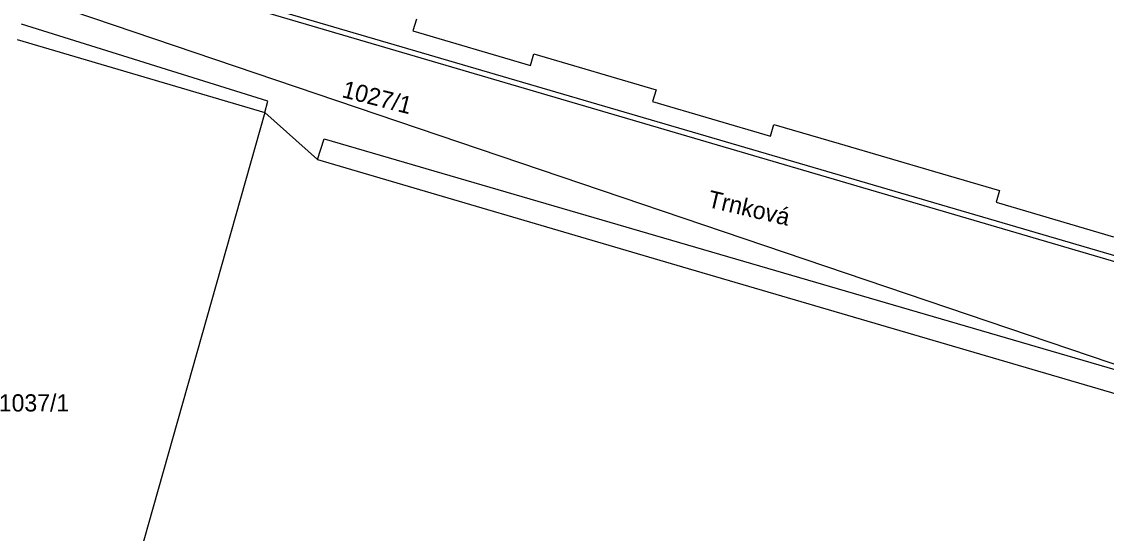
# Model space of a CAD drawing. Extents: x -469926 to -462499, y -1098642 to -1092733.
# Drawn here: x -465329.9 to -465222.8, y -1095231.4 to -1095180.8 of the extents above; entities that cross this region are included whole.
import ezdxf

# ---------------------------------------------------------------- set-up
doc = ezdxf.new("R2010")
doc.units = 0
for name, color, linetype in [('Vrstva 1', 7, 'Continuous'), ('Vrstva 4', 7, 'Continuous'), ('Vrstva 50', 7, 'Continuous'), ('Vrstva 6', 7, 'Continuous'), ('Vrstva 8', 7, 'Continuous')]:
    doc.layers.add(name, color=color, linetype=linetype)

msp = doc.modelspace()

# ---------------------------------------------------------------- linework, layer by layer
at = {"layer": 'Vrstva 1'}
for p, q in [((-465290.92, -1095180.57), (-465291.27, -1095181.74)), ((-465290.92, -1095180.57), (-465291.27, -1095181.74)), ((-465291.27, -1095181.74), (-465279.67, -1095185.14)), ((-465291.27, -1095181.74), (-465279.67, -1095185.14)), ((-465330.39, -1095182.57), (-465305.92, -1095189.78)), ((-465279.67, -1095185.14), (-465279.32, -1095183.99)), ((-465279.67, -1095185.14), (-465279.32, -1095183.99)), ((-465279.32, -1095183.99), (-465267.25, -1095187.55)), ((-465279.32, -1095183.99), (-465267.25, -1095187.55)), ((-465267.25, -1095187.55), (-465267.59, -1095188.7)), ((-465267.25, -1095187.55), (-465267.59, -1095188.7)), ((-465267.59, -1095188.7), (-465255.95, -1095192.13)), ((-465267.59, -1095188.7), (-465255.95, -1095192.13)), ((-465305.92, -1095189.78), (-465325.28, -1095258.28)), ((-465305.92, -1095189.78), (-465325.28, -1095258.28)), ((-465305.92, -1095189.78), (-465300.7, -1095194.45)), ((-465305.92, -1095189.78), (-465300.7, -1095194.45)), ((-465255.95, -1095192.13), (-465255.61, -1095190.99)), ((-465255.95, -1095192.13), (-465255.61, -1095190.99)), ((-465255.61, -1095190.99), (-465249.16, -1095192.86)), ((-465255.61, -1095190.99), (-465249.16, -1095192.86)), ((-465249.16, -1095192.86), (-465239.73, -1095195.62)), ((-465249.16, -1095192.86), (-465239.73, -1095195.62)), ((-465300.7, -1095194.45), (-465264.63, -1095205.04)), ((-465300.7, -1095194.45), (-465264.63, -1095205.04)), ((-465239.73, -1095195.62), (-465233.31, -1095197.5)), ((-465239.73, -1095195.62), (-465233.31, -1095197.5)), ((-465233.31, -1095197.5), (-465233.65, -1095198.64)), ((-465233.31, -1095197.5), (-465233.65, -1095198.64)), ((-465233.65, -1095198.64), (-465222.05, -1095202.07)), ((-465233.65, -1095198.64), (-465222.05, -1095202.07)), ((-465264.63, -1095205.04), (-465241.83, -1095211.72)), ((-465264.63, -1095205.04), (-465241.83, -1095211.72)), ((-465241.83, -1095211.72), (-465205.75, -1095222.31)), ((-465241.83, -1095211.72), (-465205.75, -1095222.31))]:
    msp.add_line(p, q, dxfattribs=at)
at = {"layer": 'Vrstva 4'}
for p, q in [((-465189.34, -1095214.13), (-465355.8, -1095165.21)), ((-465305.6, -1095188.68), (-465329.95, -1095181.07)), ((-465305.92, -1095189.78), (-465305.6, -1095188.68)), ((-465305.92, -1095189.78), (-465305.6, -1095188.68)), ((-465300.7, -1095194.45), (-465300.06, -1095192.41)), ((-465300.7, -1095194.45), (-465300.06, -1095192.41)), ((-465300.06, -1095192.41), (-465194.72, -1095223.14)), ((-465300.06, -1095192.41), (-465194.72, -1095223.14))]:
    msp.add_line(p, q, dxfattribs=at)
at = {"layer": 'Vrstva 6'}
msp.add_line((-465181.83, -1095228.27), (-465368.22, -1095165.09), dxfattribs=at)
at = {"layer": 'Vrstva 8'}
msp.add_line((-465179.3, -1095216.47), (-465368.14, -1095161.1), dxfattribs=at)

# ---------------------------------------------------------------- texts
at = {"layer": 'Vrstva 50'}
for s, rotation, p in [('1027/1', 345.726, (-465298.38, -1095188.26)), ('Trnková', 346.698, (-465262.26, -1095199.11))]:
    msp.add_text(s, height=1.7, rotation=rotation, dxfattribs=at).set_placement(p)
msp.add_text('1037/1', height=1.7, dxfattribs=at).set_placement((-465332.19, -1095219.34))

doc.saveas('drawing.dxf')
